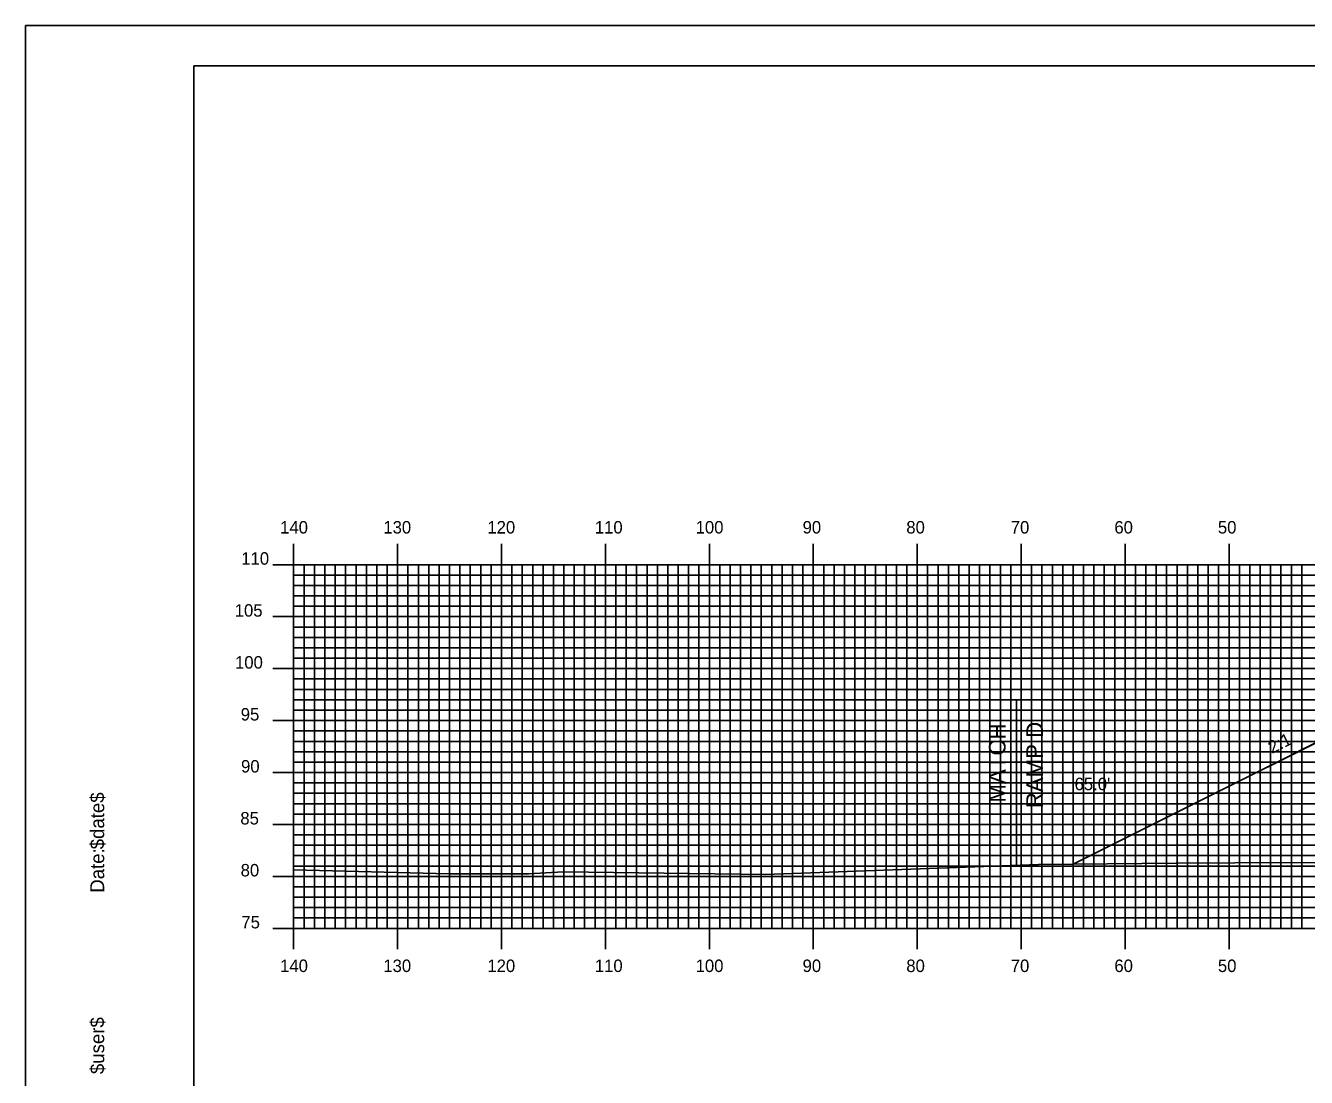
# Model space of a CAD drawing. Extents: x 1755888 to 1756232, y 442591 to 442811.
# Drawn here: x 1755888.3 to 1756011.5, y 442709.3 to 442810.5 of the extents above; entities that cross this region are included whole.
import ezdxf

# ---------------------------------------------------------------- set-up
doc = ezdxf.new("R2010")
doc.units = 0
for name, color, linetype in [('ANNOTATION', 7, 'Continuous'), ('BORDER', 7, 'Continuous'), ('D_Roadway_Centerline', 7, 'Continuous'), ('D_Roadway_SlopeLines', 7, 'Continuous'), ('D_Roadway_SubGrade', 7, 'Continuous'), ('D_Text_Standard', 7, 'Continuous'), ('H_V ANNOTATION', 7, 'Continuous'), ('MAJOR', 7, 'Continuous'), ('MINOR', 7, 'Continuous'), ('PLOT BOUNDARY', 7, 'Continuous'), ('S_Roadway_Centerline', 7, 'Continuous')]:
    doc.layers.add(name, color=color, linetype=linetype)

msp = doc.modelspace()

# ---------------------------------------------------------------- linework, layer by layer
at = {"layer": 'ANNOTATION'}
msp.add_line((1755983.6, 442729.73), (1755983.6, 442738.08), dxfattribs=at)
at = {"layer": 'BORDER'}
msp.add_lwpolyline([(1755904.46, 442596.67), (1756224.46, 442596.67), (1756224.46, 442806.67), (1755904.46, 442806.67)], close=True, dxfattribs=at)
at = {"layer": 'D_Roadway_Centerline'}
msp.add_lwpolyline([(1755989.06, 442729.85), (1756026.31, 442748.47), (1756031.06, 442750.85), (1756034.06, 442750.97), (1756042.06, 442751.29), (1756054.06, 442751.53), (1756066.06, 442751.29), (1756066.24, 442751.28), (1756076.73, 442750.8), (1756078.79, 442750.7), (1756080.93, 442750.6), (1756086.8, 442750.32), (1756088.3, 442750.25), (1756089.8, 442750.18), (1756096.45, 442747.96), (1756098.5, 442747.28), (1756103.73, 442745.53), (1756120.4, 442739.96), (1756133.71, 442735.51), (1756138.61, 442733.87), (1756146.45, 442731.25)], dxfattribs=at)
at = {"layer": 'D_Roadway_SlopeLines'}
msp.add_lwpolyline([(1756031.06, 442750.85), (1755989.06, 442729.85)], dxfattribs=at)
at = {"layer": 'D_Roadway_SubGrade'}
msp.add_line((1755983.6, 442745.68), (1755983.6, 442729.73), dxfattribs=at)
at = {"layer": 'MAJOR'}
for p, q in [((1755914.06, 442760.67), (1755914.06, 442758.67)), ((1755924.06, 442760.67), (1755924.06, 442758.67)), ((1755934.06, 442760.67), (1755934.06, 442758.67)), ((1755944.06, 442760.67), (1755944.06, 442758.67)), ((1755954.06, 442760.67), (1755954.06, 442758.67)), ((1755964.06, 442760.67), (1755964.06, 442758.67)), ((1755974.06, 442760.67), (1755974.06, 442758.67)), ((1755984.06, 442760.67), (1755984.06, 442758.67)), ((1755994.06, 442760.67), (1755994.06, 442758.67)), ((1756004.06, 442760.67), (1756004.06, 442758.67)), ((1755912.05, 442758.67), (1755914.06, 442758.67)), ((1755914.06, 442758.67), (1756194.06, 442758.67)), ((1755914.06, 442723.67), (1755914.06, 442758.67)), ((1755914.06, 442723.67), (1755914.06, 442758.67)), ((1755914.06, 442758.67), (1756194.06, 442758.67)), ((1755924.06, 442723.67), (1755924.06, 442758.67)), ((1755934.06, 442723.67), (1755934.06, 442758.67)), ((1755944.06, 442723.67), (1755944.06, 442758.67)), ((1755954.06, 442723.67), (1755954.06, 442758.67)), ((1755964.06, 442723.67), (1755964.06, 442758.67)), ((1755974.06, 442723.67), (1755974.06, 442758.67)), ((1755984.06, 442723.67), (1755984.06, 442758.67)), ((1755994.06, 442723.67), (1755994.06, 442758.67)), ((1756004.06, 442723.67), (1756004.06, 442758.67)), ((1755912.05, 442753.67), (1755914.06, 442753.67)), ((1755914.06, 442753.67), (1756194.06, 442753.67)), ((1755912.05, 442748.67), (1755914.06, 442748.67)), ((1755914.06, 442748.67), (1756194.06, 442748.67)), ((1755912.05, 442743.67), (1755914.06, 442743.67)), ((1755914.06, 442743.67), (1756194.06, 442743.67)), ((1755912.05, 442738.67), (1755914.06, 442738.67)), ((1755914.06, 442738.67), (1756194.06, 442738.67)), ((1755912.05, 442733.67), (1755914.06, 442733.67)), ((1755914.06, 442733.67), (1756194.06, 442733.67)), ((1755912.05, 442728.67), (1755914.06, 442728.67)), ((1755914.06, 442728.67), (1756194.06, 442728.67)), ((1755912.05, 442723.67), (1755914.06, 442723.67)), ((1755914.06, 442723.67), (1756194.06, 442723.67)), ((1755914.06, 442723.67), (1756194.06, 442723.67)), ((1755914.06, 442721.66), (1755914.06, 442723.67)), ((1755924.06, 442721.66), (1755924.06, 442723.67)), ((1755934.06, 442721.66), (1755934.06, 442723.67)), ((1755944.06, 442721.66), (1755944.06, 442723.67)), ((1755954.06, 442721.66), (1755954.06, 442723.67)), ((1755964.06, 442721.66), (1755964.06, 442723.67)), ((1755974.06, 442721.66), (1755974.06, 442723.67)), ((1755984.06, 442721.66), (1755984.06, 442723.67)), ((1755994.06, 442721.66), (1755994.06, 442723.67)), ((1756004.06, 442721.66), (1756004.06, 442723.67))]:
    msp.add_line(p, q, dxfattribs=at)
at = {"layer": 'MINOR'}
for p, q in [((1755915.06, 442723.67), (1755915.06, 442758.67)), ((1755916.06, 442723.67), (1755916.06, 442758.67)), ((1755917.06, 442723.67), (1755917.06, 442758.67)), ((1755918.06, 442723.67), (1755918.06, 442758.67)), ((1755919.06, 442723.67), (1755919.06, 442758.67)), ((1755920.06, 442723.67), (1755920.06, 442758.67)), ((1755921.06, 442723.67), (1755921.06, 442758.67)), ((1755922.06, 442723.67), (1755922.06, 442758.67)), ((1755923.06, 442723.67), (1755923.06, 442758.67)), ((1755925.06, 442723.67), (1755925.06, 442758.67)), ((1755926.06, 442723.67), (1755926.06, 442758.67)), ((1755927.06, 442723.67), (1755927.06, 442758.67)), ((1755928.06, 442723.67), (1755928.06, 442758.67)), ((1755929.06, 442723.67), (1755929.06, 442758.67)), ((1755930.06, 442723.67), (1755930.06, 442758.67)), ((1755931.06, 442723.67), (1755931.06, 442758.67)), ((1755932.06, 442723.67), (1755932.06, 442758.67)), ((1755933.06, 442723.67), (1755933.06, 442758.67)), ((1755935.06, 442723.67), (1755935.06, 442758.67)), ((1755936.06, 442723.67), (1755936.06, 442758.67)), ((1755937.06, 442723.67), (1755937.06, 442758.67)), ((1755938.06, 442723.67), (1755938.06, 442758.67)), ((1755939.06, 442723.67), (1755939.06, 442758.67)), ((1755940.06, 442723.67), (1755940.06, 442758.67)), ((1755941.06, 442723.67), (1755941.06, 442758.67)), ((1755942.06, 442723.67), (1755942.06, 442758.67)), ((1755943.06, 442723.67), (1755943.06, 442758.67)), ((1755945.06, 442723.67), (1755945.06, 442758.67)), ((1755946.06, 442723.67), (1755946.06, 442758.67)), ((1755947.06, 442723.67), (1755947.06, 442758.67)), ((1755948.06, 442723.67), (1755948.06, 442758.67)), ((1755949.06, 442723.67), (1755949.06, 442758.67)), ((1755950.06, 442723.67), (1755950.06, 442758.67)), ((1755951.06, 442723.67), (1755951.06, 442758.67)), ((1755952.06, 442723.67), (1755952.06, 442758.67)), ((1755953.06, 442723.67), (1755953.06, 442758.67)), ((1755955.06, 442723.67), (1755955.06, 442758.67)), ((1755956.06, 442723.67), (1755956.06, 442758.67)), ((1755957.06, 442723.67), (1755957.06, 442758.67)), ((1755958.06, 442723.67), (1755958.06, 442758.67)), ((1755959.06, 442723.67), (1755959.06, 442758.67)), ((1755960.06, 442723.67), (1755960.06, 442758.67)), ((1755961.06, 442723.67), (1755961.06, 442758.67)), ((1755962.06, 442723.67), (1755962.06, 442758.67)), ((1755963.06, 442723.67), (1755963.06, 442758.67)), ((1755965.06, 442723.67), (1755965.06, 442758.67)), ((1755966.06, 442723.67), (1755966.06, 442758.67)), ((1755967.06, 442723.67), (1755967.06, 442758.67)), ((1755968.06, 442723.67), (1755968.06, 442758.67)), ((1755969.06, 442723.67), (1755969.06, 442758.67)), ((1755970.06, 442723.67), (1755970.06, 442758.67)), ((1755971.06, 442723.67), (1755971.06, 442758.67)), ((1755972.06, 442723.67), (1755972.06, 442758.67)), ((1755973.06, 442723.67), (1755973.06, 442758.67)), ((1755975.06, 442723.67), (1755975.06, 442758.67)), ((1755976.06, 442723.67), (1755976.06, 442758.67)), ((1755977.06, 442723.67), (1755977.06, 442758.67)), ((1755978.06, 442723.67), (1755978.06, 442758.67)), ((1755979.06, 442723.67), (1755979.06, 442758.67)), ((1755980.06, 442723.67), (1755980.06, 442758.67)), ((1755981.06, 442723.67), (1755981.06, 442758.67)), ((1755982.06, 442723.67), (1755982.06, 442758.67)), ((1755983.06, 442723.67), (1755983.06, 442758.67)), ((1755985.06, 442723.67), (1755985.06, 442758.67)), ((1755986.06, 442723.67), (1755986.06, 442758.67)), ((1755987.06, 442723.67), (1755987.06, 442758.67)), ((1755988.06, 442723.67), (1755988.06, 442758.67)), ((1755989.06, 442723.67), (1755989.06, 442758.67)), ((1755990.06, 442723.67), (1755990.06, 442758.67)), ((1755991.06, 442723.67), (1755991.06, 442758.67)), ((1755992.06, 442723.67), (1755992.06, 442758.67)), ((1755993.06, 442723.67), (1755993.06, 442758.67)), ((1755995.06, 442723.67), (1755995.06, 442758.67)), ((1755996.06, 442723.67), (1755996.06, 442758.67)), ((1755997.06, 442723.67), (1755997.06, 442758.67)), ((1755998.06, 442723.67), (1755998.06, 442758.67)), ((1755999.06, 442723.67), (1755999.06, 442758.67)), ((1756000.06, 442723.67), (1756000.06, 442758.67)), ((1756001.06, 442723.67), (1756001.06, 442758.67)), ((1756002.06, 442723.67), (1756002.06, 442758.67)), ((1756003.06, 442723.67), (1756003.06, 442758.67)), ((1756005.06, 442723.67), (1756005.06, 442758.67)), ((1756006.06, 442723.67), (1756006.06, 442758.67)), ((1756007.06, 442723.67), (1756007.06, 442758.67)), ((1756008.06, 442723.67), (1756008.06, 442758.67)), ((1756009.06, 442723.67), (1756009.06, 442758.67)), ((1756010.06, 442723.67), (1756010.06, 442758.67)), ((1756011.06, 442723.67), (1756011.06, 442758.67)), ((1755914.06, 442757.67), (1756194.06, 442757.67)), ((1755914.06, 442757.67), (1755916.06, 442757.67)), ((1755914.06, 442756.67), (1756194.06, 442756.67)), ((1755914.06, 442756.67), (1755916.06, 442756.67)), ((1755914.06, 442755.67), (1756194.06, 442755.67)), ((1755914.06, 442755.67), (1755916.06, 442755.67)), ((1755914.06, 442754.67), (1756194.06, 442754.67)), ((1755914.06, 442754.67), (1755916.06, 442754.67)), ((1755914.06, 442752.67), (1756194.06, 442752.67)), ((1755914.06, 442752.67), (1755916.06, 442752.67)), ((1755914.06, 442751.67), (1756194.06, 442751.67)), ((1755914.06, 442751.67), (1755916.06, 442751.67)), ((1755914.06, 442750.67), (1756194.06, 442750.67)), ((1755914.06, 442750.67), (1755916.06, 442750.67)), ((1755914.06, 442749.67), (1756194.06, 442749.67)), ((1755914.06, 442749.67), (1755916.06, 442749.67)), ((1755914.06, 442747.67), (1756194.06, 442747.67)), ((1755914.06, 442747.67), (1755916.06, 442747.67)), ((1755914.06, 442746.67), (1756194.06, 442746.67)), ((1755914.06, 442746.67), (1755916.06, 442746.67)), ((1755914.06, 442745.67), (1756194.06, 442745.67)), ((1755914.06, 442745.67), (1755916.06, 442745.67)), ((1755914.06, 442744.67), (1756194.06, 442744.67)), ((1755914.06, 442744.67), (1755916.06, 442744.67)), ((1755914.06, 442742.67), (1756194.06, 442742.67)), ((1755914.06, 442742.67), (1755916.06, 442742.67)), ((1755914.06, 442741.67), (1756194.06, 442741.67)), ((1755914.06, 442741.67), (1755916.06, 442741.67)), ((1755914.06, 442740.67), (1756194.06, 442740.67)), ((1755914.06, 442740.67), (1755916.06, 442740.67)), ((1755914.06, 442739.67), (1756194.06, 442739.67)), ((1755914.06, 442739.67), (1755916.06, 442739.67)), ((1755914.06, 442737.67), (1756194.06, 442737.67)), ((1755914.06, 442737.67), (1755916.06, 442737.67)), ((1755914.06, 442736.67), (1756194.06, 442736.67)), ((1755914.06, 442736.67), (1755916.06, 442736.67)), ((1755914.06, 442735.67), (1756194.06, 442735.67)), ((1755914.06, 442735.67), (1755916.06, 442735.67)), ((1755914.06, 442734.67), (1756194.06, 442734.67)), ((1755914.06, 442734.67), (1755916.06, 442734.67)), ((1755914.06, 442732.67), (1756194.06, 442732.67)), ((1755914.06, 442732.67), (1755916.06, 442732.67)), ((1755914.06, 442731.67), (1756194.06, 442731.67)), ((1755914.06, 442731.67), (1755916.06, 442731.67)), ((1755914.06, 442730.67), (1756194.06, 442730.67)), ((1755914.06, 442730.67), (1755916.06, 442730.67)), ((1755914.06, 442729.67), (1756194.06, 442729.67)), ((1755914.06, 442729.67), (1755916.06, 442729.67)), ((1755914.06, 442727.67), (1756194.06, 442727.67)), ((1755914.06, 442727.67), (1755916.06, 442727.67)), ((1755914.06, 442726.67), (1756194.06, 442726.67)), ((1755914.06, 442726.67), (1755916.06, 442726.67)), ((1755914.06, 442725.67), (1756194.06, 442725.67)), ((1755914.06, 442725.67), (1755916.06, 442725.67)), ((1755914.06, 442724.67), (1756194.06, 442724.67)), ((1755914.06, 442724.67), (1755916.06, 442724.67))]:
    msp.add_line(p, q, dxfattribs=at)
at = {"layer": 'PLOT BOUNDARY'}
msp.add_lwpolyline([(1755888.27, 442590.55), (1756228.27, 442590.55), (1756228.27, 442810.55), (1755888.27, 442810.55)], close=True, dxfattribs=at)
at = {"layer": 'S_Roadway_Centerline'}
msp.add_lwpolyline([(1755914.06, 442729.3), (1755929.02, 442728.93), (1755936.66, 442728.91), (1755939.99, 442729.1), (1755959.43, 442728.85), (1755985.74, 442729.81), (1755998.98, 442729.96), (1756004.62, 442729.97), (1756047.7, 442730.01), (1756053.19, 442730.1), (1756057.32, 442730.2), (1756075.29, 442730.61), (1756080.95, 442730.51), (1756083.99, 442730.88), (1756088.01, 442730.38), (1756098.56, 442731.95), (1756111.81, 442731.35), (1756118.83, 442730.91), (1756130.1, 442730.66), (1756146.83, 442731.27), (1756164.74, 442730.34), (1756179.2, 442730.36), (1756189.71, 442730.46), (1756194.06, 442730.48)], dxfattribs=at)

# ---------------------------------------------------------------- texts
at = {"layer": 'ANNOTATION'}
for s, height, rotation, p in [('MATCH', 1.6, 90, (1755982.56, 442735.78)), ('RAMP D', 1.6, 90, (1755986.16, 442735.23)), ('2:1', 1.2, 26.5651, (1756008.2, 442740.46))]:
    msp.add_text(s, height=height, rotation=rotation, dxfattribs=at).set_placement(p)
at = {"layer": 'BORDER'}
for s, p in [('$date$', (1755895.83, 442731.28)), ('$date$', (1755895.83, 442731.28)), ('Date:', (1755895.83, 442727.1)), ('Date:', (1755895.83, 442727.1)), ('$user$', (1755895.83, 442709.65)), ('$user$', (1755895.83, 442709.65))]:
    msp.add_text(s, height=1.339, rotation=90, dxfattribs=at).set_placement(p)
at = {"layer": 'D_Text_Standard'}
msp.add_text("65.0'", height=1.2, dxfattribs=at).set_placement((1755989.2, 442736.97))
at = {"layer": 'H_V ANNOTATION'}
for s, p in [('140', (1755912.76, 442761.67)), ('130', (1755922.69, 442761.67)), ('120', (1755932.7, 442761.67)), ('110', (1755943.04, 442761.67)), ('100', (1755952.74, 442761.67)), ('90', (1755963.03, 442761.67)), ('80', (1755973.01, 442761.67)), ('70', (1755983.06, 442761.67)), ('60', (1755993.03, 442761.67)), ('50', (1756002.99, 442761.67)), ('110', (1755909.02, 442758.67)), ('105', (1755908.39, 442753.67)), ('100', (1755908.42, 442748.67)), ('95', (1755908.97, 442743.67)), ('90', (1755909, 442738.67)), ('85', (1755908.93, 442733.67)), ('80', (1755908.96, 442728.67)), ('75', (1755909.03, 442723.67)), ('140', (1755912.76, 442719.47)), ('130', (1755922.69, 442719.47)), ('120', (1755932.7, 442719.47)), ('110', (1755943.04, 442719.47)), ('100', (1755952.74, 442719.47)), ('90', (1755963.03, 442719.47)), ('80', (1755973.01, 442719.47)), ('70', (1755983.06, 442719.47)), ('60', (1755993.03, 442719.47)), ('50', (1756002.99, 442719.47))]:
    msp.add_text(s, height=1.2, dxfattribs=at).set_placement(p)
at = {"layer": 'MAJOR'}
msp.add_text('-', height=0.012, dxfattribs=at).set_placement((1755914.05, 442723.67))

doc.saveas('drawing.dxf')
